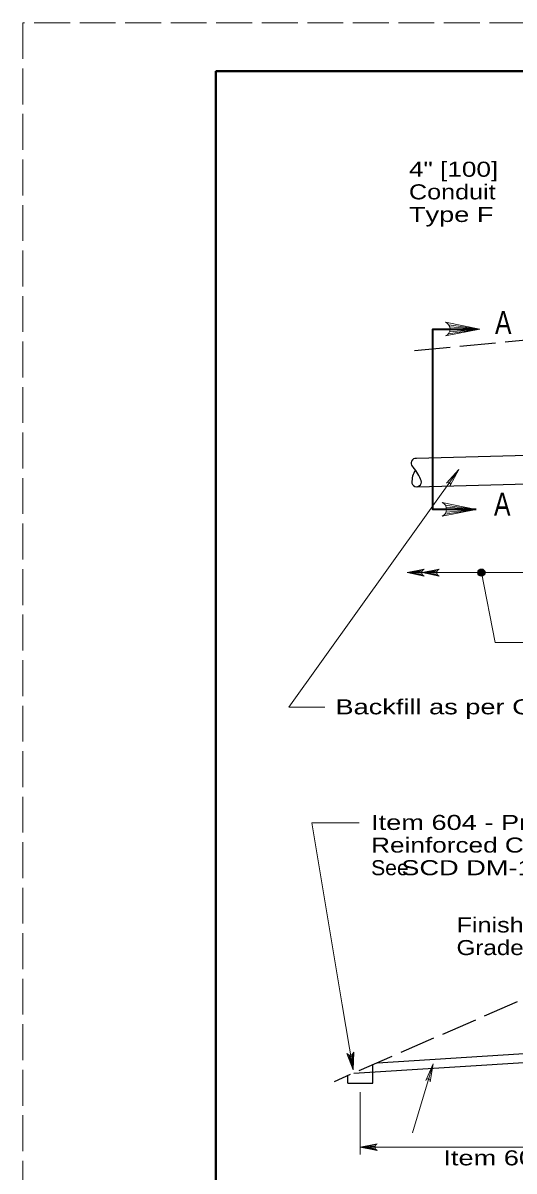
# Model space of a CAD drawing. Extents: x 743.9 to 777.9, y 1051 to 1073.
# Drawn here: x 743.86 to 748.95, y 1061.11 to 1073.02 of the extents above; entities that cross this region are included whole.
import ezdxf
from ezdxf.enums import TextEntityAlignment as Align

# ---------------------------------------------------------------- set-up
doc = ezdxf.new("R2010")
doc.units = 0
doc.header["$LTSCALE"] = 0.062
doc.linetypes.add('LONG_DASHED', pattern=[7.5, 6, -1.5])
doc.layers.add('1', color=7, linetype='Continuous', lineweight=13)
doc.layers.add('47', color=7, linetype='Continuous', lineweight=13)

msp = doc.modelspace()

# ---------------------------------------------------------------- hatches: boundary and pattern name
at = {"layer": '1'}
msp.add_hatch(color=256, dxfattribs=at).paths.add_polyline_path([(748.6528, 1067.31818, 1), (748.57823, 1067.31818, 1)])

# ---------------------------------------------------------------- linework, layer by layer
at = {"layer": '1', "lineweight": 25}
for p, q in [((745.86317, 1072.51808), (777.36317, 1072.51808)), ((747.94125, 1068.50342), (749.93525, 1068.55775)), ((747.95033, 1068.20867), (749.9415, 1068.26283)), ((747.53925, 1062.23575), (754.00342, 1062.64917)), ((747.29233, 1062.12783), (749.631, 1062.27417)), ((747.49092, 1062.02392), (747.49092, 1062.21467)), ((747.23233, 1062.02392), (747.49092, 1062.02392)), ((747.2325, 1062.02433), (747.2325, 1062.0995))]:
    msp.add_line(p, q, dxfattribs=at)
at = {"layer": '1', "linetype": 'LONG_DASHED', "lineweight": 25}
for p, q in [((747.92125, 1069.62217), (751.86733, 1069.99925)), ((749.85042, 1063.24492), (747.08767, 1062.03908))]:
    msp.add_line(p, q, dxfattribs=at)
at = {"layer": '1'}
for p, q in [((748.27792, 1069.88767), (748.59842, 1069.84283)), ((748.28883, 1069.8655), (748.59842, 1069.84283)), ((748.27417, 1069.79325), (748.59842, 1069.84283)), ((748.28642, 1069.814), (748.59842, 1069.84283)), ((748.29208, 1069.84283), (748.59842, 1069.84283)), ((748.23692, 1067.92425), (748.56117, 1067.97383)), ((748.24067, 1068.01867), (748.56117, 1067.97383)), ((748.24917, 1067.945), (748.56117, 1067.97383)), ((748.2515, 1067.9965), (748.56117, 1067.97383)), ((748.25483, 1067.97383), (748.56117, 1067.97383)), ((748.00492, 1067.34025), (747.84467, 1067.31783)), ((747.9995, 1067.32917), (747.84467, 1067.31783)), ((747.99783, 1067.31783), (747.84467, 1067.31783)), ((748.00067, 1067.30342), (747.84467, 1067.31783)), ((748.00683, 1067.293), (747.84467, 1067.31783)), ((748.16025, 1067.34), (748, 1067.31758)), ((748.15483, 1067.32892), (748, 1067.31758)), ((748.15317, 1067.31758), (748, 1067.31758)), ((748.156, 1067.30317), (748, 1067.31758)), ((748.16217, 1067.29275), (748, 1067.31758)), ((746.85725, 1064.72192), (747.34858, 1064.72192)), ((747.23767, 1062.31792), (747.28608, 1062.1635)), ((747.2495, 1062.31433), (747.28608, 1062.1635)), ((747.26092, 1062.31458), (747.28608, 1062.1635)), ((747.27467, 1062.31975), (747.28608, 1062.1635)), ((747.28392, 1062.3275), (747.28608, 1062.1635)), ((748.11608, 1062.22525), (747.90008, 1061.50858)), ((747.35933, 1061.28242), (747.35933, 1061.929)), ((747.51958, 1061.38258), (747.35933, 1061.36017)), ((747.51417, 1061.3715), (747.35933, 1061.36017)), ((747.5125, 1061.36017), (747.35933, 1061.36017)), ((747.51533, 1061.34583), (747.35933, 1061.36017)), ((747.5215, 1061.33542), (747.35933, 1061.36017)), ((747.35933, 1061.36017), (754.09783, 1061.36017))]:
    msp.add_line(p, q, dxfattribs=at)
at = {"layer": '1', "linetype": 'LONG_DASHED'}
msp.add_lwpolyline([(743.86317, 1051.01808), (777.86317, 1051.01808), (777.86317, 1073.01808), (743.86317, 1073.01808)], close=True, dxfattribs=at)
at = {"layer": '1', "lineweight": 25}
msp.add_lwpolyline([(777.36317, 1051.51808), (745.86317, 1051.51808), (745.86317, 1072.51808)], dxfattribs=at)
at = {"layer": '1', "lineweight": 40}
msp.add_lwpolyline([(745.86317, 1072.51808), (777.36317, 1072.51808), (777.36317, 1051.51808), (745.86317, 1051.51808)], close=True, dxfattribs=at)
msp.add_lwpolyline([(745.86317, 1072.51808), (777.36317, 1072.51808), (777.36317, 1051.51808), (745.86317, 1051.51808)], close=True, dxfattribs=at)
at = {"layer": '1'}
for points in [[(748.24442, 1069.772), (748.59842, 1069.84283), (748.24442, 1069.91367)], [(748.38108, 1068.38592), (746.61933, 1065.92167), (746.9935, 1065.92167)], [(748.20717, 1067.903), (748.56117, 1067.97383), (748.20717, 1068.04458)], [(748.02167, 1067.28242), (747.84467, 1067.31783), (748.02167, 1067.35325)], [(747.84467, 1067.31783), (748.63167, 1067.31783), (749.20083, 1067.31783)], [(748.177, 1067.28217), (748, 1067.31758), (748.177, 1067.35292)], [(748.6155, 1067.31817), (748.75717, 1066.59367), (749.0915, 1066.59367)], [(746.85725, 1064.72192), (747.1735, 1062.83417), (747.28608, 1062.16167)], [(747.29192, 1062.34392), (747.28608, 1062.1635), (747.22208, 1062.33225)], [(747.53633, 1061.32475), (747.35933, 1061.36017), (747.53633, 1061.39558)]]:
    msp.add_lwpolyline(points, dxfattribs=at)
at = {"layer": '1', "lineweight": 35}
msp.add_lwpolyline([(748.56117, 1067.97383), (748.11233, 1067.97383), (748.11233, 1069.84208), (748.56117, 1069.84208)], dxfattribs=at)
at = {"layer": '1', "lineweight": 25}
msp.add_circle((748.61552, 1067.31818), 0.03728, dxfattribs=at)
at = {"layer": '1'}
for centre, radius, start, end in [((748.21584, 1069.8429), 0.0764, 292.08605, 67.91218), ((748.17858, 1067.9739), 0.0764, 292.08605, 67.91218), ((748.03598, 1067.31785), 0.0382, 112.08782, 247.91395), ((748.19131, 1067.31759), 0.0382, 112.08782, 247.91395), ((747.25462, 1062.35219), 0.0382, 211.54189, 347.36802), ((747.55064, 1061.36023), 0.0382, 112.08782, 247.91395)]:
    msp.add_arc(centre, radius, start, end, dxfattribs=at)
at = {"layer": '1', "lineweight": 25}
for centre, radius, start, end in [((747.93696, 1068.45385), 0.04947, 85.49291, 223.16665), ((747.51133, 1068.0813), 0.51608, 23.32869, 41.98983), ((748.10677, 1068.26052), 0.21206, 145.89179, 182.57886), ((747.94397, 1068.25845), 0.04947, 175.0897, 36.00775)]:
    msp.add_arc(centre, radius, start, end, dxfattribs=at)
at = {"layer": '47'}
for points in [[(748.253, 1068.247), (748.38108, 1068.38592), (748.29108, 1068.21975)], [(748.03958, 1062.0525), (748.11608, 1062.22525), (748.08442, 1062.039)]]:
    msp.add_lwpolyline(points, dxfattribs=at)
for centre, start, end in [((748.27204, 1068.23338), 324.43814, 144.43814), ((748.06198, 1062.04572), 343.22892, 163.22892)]:
    msp.add_arc(centre, 0.02342, start, end, dxfattribs=at)

# ---------------------------------------------------------------- texts
at = {"layer": '1'}
for s, height, width, p in [('4" [100]', 0.156, 1.3, (747.86442, 1071.42333)), ('Conduit', 0.156, 1.25, (747.86442, 1071.18867)), ('Type F', 0.156, 1.35, (747.86442, 1070.954)), ('A', 0.24, 0.8, (748.75633, 1069.7915)), ('A', 0.24, 0.8, (748.74592, 1067.90825)), ('Backfill as per CMS 605.03.C', 0.156, 1.35, (747.10283, 1065.84833)), ('Item 604 - Precast', 0.156, 1.35, (747.47217, 1064.64933)), ('Reinforced Concrete Outlet', 0.156, 1.3, (747.47217, 1064.41467)), ('See', 0.156, 1.05, (747.47217, 1064.18)), ('    SCD DM-1.1 ', 0.156, 1.35, (747.47217, 1064.18)), ('Finished', 0.156, 1.25, (748.358, 1063.58642)), ('Grade', 0.156, 1.2, (748.358, 1063.35175))]:
    msp.add_text(s, height=height, dxfattribs=dict(at, width=width)).set_placement(p)
at = {"layer": '1', "width": 1.35}
msp.add_text('Item 603, 4" or 6" [100 or 150] Conduit ', height=0.156, dxfattribs=at).set_placement((750.66225, 1061.171), align=Align.CENTER)

doc.saveas('drawing.dxf')
